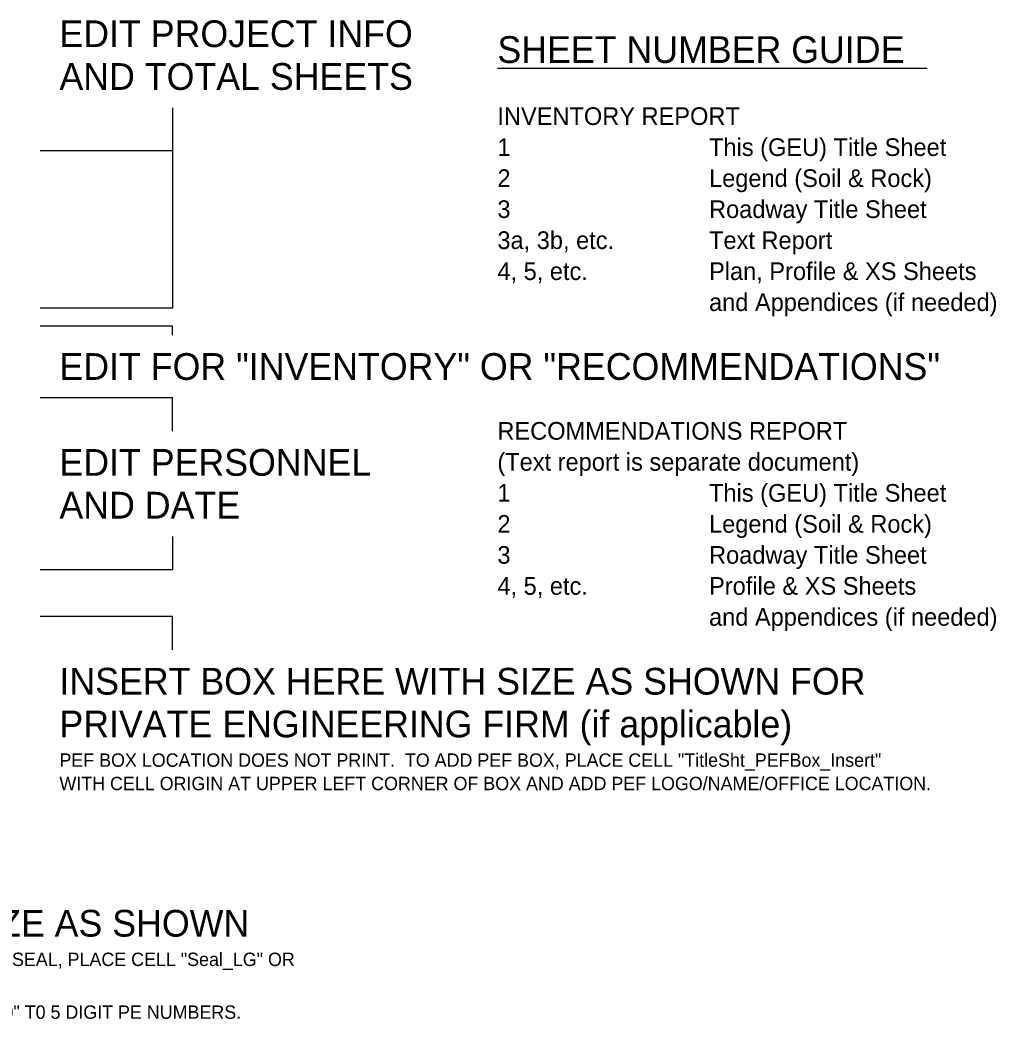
# Model space of a CAD drawing. Extents: x 265553 to 275568, y 168312 to 173522.
# Drawn here: x 268472 to 269933, y 171866 to 173361 of the extents above; entities that cross this region are included whole.
import ezdxf

# ---------------------------------------------------------------- set-up
doc = ezdxf.new("R2010")
doc.units = 0
doc.layers.add('Scratch_Level_4', color=7, linetype='Continuous')
doc.layers.add('Scratch_Level_6', color=7, linetype='Continuous')

msp = doc.modelspace()

# ---------------------------------------------------------------- linework, layer by layer
at = {"layer": 'Scratch_Level_4'}
for points in [[(268701, 173229.2), (268701, 173165), (268502.8, 173165)], [(268701, 173165), (268701, 172929.2), (268502.8, 172929.2)], [(268701, 172888.8), (268701, 172902.5), (268502.8, 172902.5)], [(268701, 172745.4), (268701, 172795.3), (268502.8, 172795.3)], [(268701, 172587.8), (268701, 172537.8), (268502.8, 172537.8)], [(268701, 172418), (268701, 172468), (268502.8, 172468)]]:
    msp.add_lwpolyline(points, dxfattribs=at)
at = {"layer": 'Scratch_Level_6'}
msp.add_line((269830.5, 173288.1), (269187.1, 173288.1), dxfattribs=at)

# ---------------------------------------------------------------- texts
at = {"layer": 'Scratch_Level_4'}
for s, height, p in [('EDIT PROJECT INFO', 40, (268531.5, 173320)), ('AND TOTAL SHEETS', 40, (268531.5, 173256)), ('EDIT FOR "INVENTORY" OR "RECOMMENDATIONS"', 40, (268531.5, 172822.1)), ('EDIT PERSONNEL', 40, (268531.5, 172678.6)), ('AND DATE', 40, (268531.5, 172614.6)), ('INSERT BOX HERE WITH SIZE AS SHOWN FOR', 40, (268531.5, 172351.2)), ('PRIVATE ENGINEERING FIRM (if applicable)', 40, (268531.5, 172287.2)), ('PEF BOX LOCATION DOES NOT PRINT.  TO ADD PEF BOX, PLACE CELL "TitleSht_PEFBox_Insert"', 20, (268531.5, 172243.2)), ('WITH CELL ORIGIN AT UPPER LEFT CORNER OF BOX AND ADD PEF LOGO/NAME/OFFICE LOCATION.', 20, (268531.5, 172208.2)), ('INSERT SEAL HERE WITH SIZE AS SHOWN', 40, (267713, 171989.1)), ('CIRCLE FOR SEAL LOCATION DOES NOT PRINT.  TO ADD SEAL, PLACE CELL "Seal_LG" OR ', 20, (267713, 171945.1)), ('PE NUMBERS SHOULD BE 6 DIGITS SO ADD A LEADING "0" T0 5 DIGIT PE NUMBERS.', 20, (267713, 171866.1))]:
    msp.add_text(s, height=height, dxfattribs=at).set_placement(p)
at = {"layer": 'Scratch_Level_6'}
for s, height, p in [('SHEET NUMBER GUIDE', 40, (269187.1, 173296.3)), ('INVENTORY REPORT', 26.4, (269187.1, 173203.5)), ('1', 26.4, (269187.1, 173157.1)), ('This (GEU) Title Sheet', 26.4, (269503.9, 173157.1)), ('2', 26.4, (269187.1, 173110.7)), ('Legend (Soil & Rock)', 26.4, (269503.9, 173110.7)), ('Roadway Title Sheet', 26.4, (269503.9, 173064.3)), ('3', 26.4, (269187.1, 173064.3)), ('3a, 3b, etc.', 26.4, (269187.1, 173017.9)), ('Text Report', 26.4, (269503.9, 173017.9)), ('4, 5, etc.', 26.4, (269187.1, 172971.5)), ('Plan, Profile & XS Sheets', 26.4, (269503.9, 172971.5)), ('and Appendices (if needed)', 26.4, (269503.9, 172925.1)), ('RECOMMENDATIONS REPORT', 26.4, (269187.1, 172732.6)), ('(Text report is separate document)', 26.4, (269187.1, 172686.2)), ('1', 26.4, (269187.1, 172639.8)), ('This (GEU) Title Sheet', 26.4, (269503.9, 172639.8)), ('2', 26.4, (269187.1, 172593.4)), ('Legend (Soil & Rock)', 26.4, (269503.9, 172593.4)), ('3', 26.4, (269187.1, 172547)), ('Roadway Title Sheet', 26.4, (269503.9, 172547)), ('4, 5, etc.', 26.4, (269187.1, 172500.6)), ('Profile & XS Sheets', 26.4, (269503.9, 172500.6)), ('and Appendices (if needed)', 26.4, (269503.9, 172454.2))]:
    msp.add_text(s, height=height, dxfattribs=at).set_placement(p)

doc.saveas('drawing.dxf')
